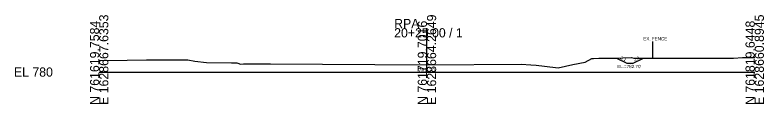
# Model space of a CAD drawing. Extents: x -26 to 203, y 990 to 7517.
# Drawn here: x -25.7 to 202.8, y 4490.3 to 4517.3 of the extents above; entities that cross this region are included whole.
import ezdxf

# ---------------------------------------------------------------- set-up
doc = ezdxf.new("R2010")
doc.units = 0
for name, color, linetype in [('Exist Cross Section Cell', 7, 'Continuous'), ('Exist XS Center Line Elevation Label', 7, 'Continuous'), ('Exist XS Ground Line', 7, 'Continuous'), ('Prop XS DDE', 7, 'Continuous'), ('Prop XS DDE Elevations', 7, 'Continuous'), ('Prop XS Side Slope Text', 7, 'Continuous')]:
    doc.layers.add(name, color=color, linetype=linetype)

msp = doc.modelspace()

# ---------------------------------------------------------------- linework, layer by layer
at = {"layer": 'Exist Cross Section Cell'}
for p, q in [((100, 4500), (100, 4513.33)), ((0, 4500), (100, 4500)), ((100, 4500), (200, 4500))]:
    msp.add_line(p, q, dxfattribs=at)
at = {"layer": 'Exist XS Ground Line'}
for p, q in [((168.95, 4504.25), (168.95, 4509.25)), ((159.78, 4504.28), (162.43, 4504.38)), ((162.43, 4504.38), (163.1, 4504.26)), ((193.55, 4504.24), (196.32, 4504.39)), ((196.32, 4504.39), (197.1, 4504.4)), ((197.1, 4504.4), (198.09, 4504.43)), ((198.09, 4504.43), (199.62, 4504.44)), ((199.62, 4504.44), (200, 4504.44)), ((0, 4503.47), (8.54, 4503.64)), ((8.54, 4503.64), (14.44, 4503.75)), ((14.44, 4503.75), (24.37, 4503.69)), ((24.37, 4503.69), (27.05, 4503.7)), ((27.05, 4503.7), (29.13, 4503.3)), ((29.13, 4503.3), (32.74, 4502.9)), ((32.74, 4502.9), (40.41, 4502.84)), ((40.41, 4502.84), (42.02, 4502.82)), ((42.02, 4502.82), (42.56, 4502.64)), ((42.56, 4502.64), (42.98, 4502.39)), ((42.98, 4502.39), (44.04, 4502.45)), ((44.04, 4502.45), (44.61, 4502.49)), ((44.61, 4502.49), (52.22, 4502.5)), ((52.22, 4502.5), (100, 4502.2)), ((100, 4502.2), (128.77, 4502.41)), ((128.77, 4502.41), (131.71, 4502.2)), ((131.71, 4502.2), (133.28, 4502.1)), ((133.28, 4502.1), (139.18, 4501.41)), ((140.05, 4501.33), (144.55, 4502.32)), ((144.55, 4502.32), (148.29, 4503.05)), ((148.29, 4503.05), (150.33, 4504.11)), ((150.33, 4504.11), (150.8, 4504.09)), ((150.8, 4504.09), (152.45, 4504.23)), ((152.45, 4504.23), (152.81, 4504.27)), ((152.81, 4504.27), (159.78, 4504.28)), ((163.1, 4504.26), (178.52, 4504.22)), ((178.52, 4504.22), (185.71, 4504.2)), ((185.71, 4504.2), (193.55, 4504.24)), ((139.18, 4501.41), (140.05, 4501.33))]:
    msp.add_line(p, q, dxfattribs=at)
at = {"layer": 'Prop XS DDE'}
for p, q in [((152.81, 4504.27), (157.81, 4504.27)), ((157.81, 4504.27), (160.95, 4502.7)), ((160.95, 4502.7), (162.95, 4502.7)), ((162.95, 4502.7), (166.06, 4504.25))]:
    msp.add_line(p, q, dxfattribs=at)

# ---------------------------------------------------------------- texts
at = {"layer": 'Exist Cross Section Cell'}
for s, p in [('E 1628667.6353', (2.8, 4490)), ('E 1628664.2649', (102.8, 4490)), ('E 1628660.8945', (202.8, 4490)), ('N 761619.7584', (0, 4490)), ('N 761719.7016', (100, 4490)), ('N 761819.6448', (200, 4490))]:
    msp.add_text(s, height=2.8, rotation=90, dxfattribs=at).set_placement(p)
for s, p in [('RPA', (90, 4513.33)), ('20+25.00 / 1', (90, 4510.53)), ('EL 780', (-26, 4498.6))]:
    msp.add_text(s, height=2.8, dxfattribs=at).set_placement(p)
at = {"layer": 'Exist XS Center Line Elevation Label'}
msp.add_text('782.20', height=1.2, dxfattribs=at).set_placement((97.38, 4500))
at = {"layer": 'Exist XS Ground Line'}
msp.add_text('EX. FENCE', height=1, dxfattribs=at).set_placement((166.01, 4509.62))
at = {"layer": 'Prop XS DDE Elevations'}
msp.add_text("EL.=782.70'", height=1, dxfattribs=at).set_placement((158.05, 4501.19))
at = {"layer": 'Prop XS Side Slope Text'}
for rotation, p in [(333.5035, (158.86, 4504.05)), (25.9725, (163.35, 4503.2))]:
    msp.add_text('2:1', height=1, rotation=rotation, dxfattribs=at).set_placement(p)

doc.saveas('drawing.dxf')
